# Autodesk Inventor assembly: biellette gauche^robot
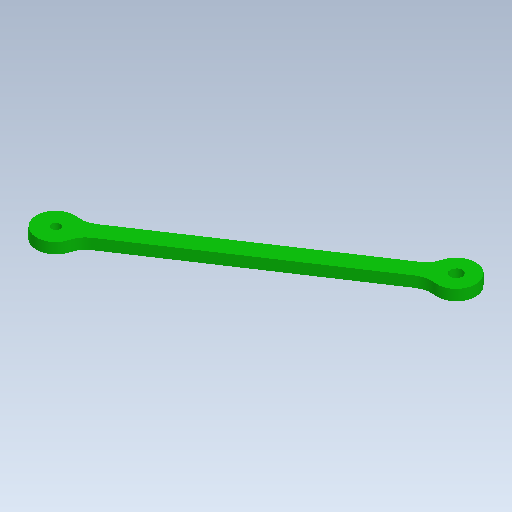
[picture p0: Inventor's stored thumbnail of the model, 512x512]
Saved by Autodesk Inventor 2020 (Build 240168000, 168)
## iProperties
Created: 2018-10
Part Number: biellette gauche^robot
Document SubType Name: Assembly
Designer: bruno
Sending System: SolidWorks 2016
Last Author: Prof
Last Saved: 2018-10-03
Author: bruno
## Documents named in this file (2)
- C:\Users\bruno\Documents\Systèmes\Mallette Bras robotisé (273265)\Dossier ressources\Maquette Dobot SW2016\biellette gauche^robot.iam
- C:\Users\bruno\Documents\Systèmes\Mallette Bras robotisé (273265)\Dossier ressources\Maquette Dobot SW2016\BREP_1-962.ipt
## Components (1 placed, 1 different names)
1. BREP_1-962:1
